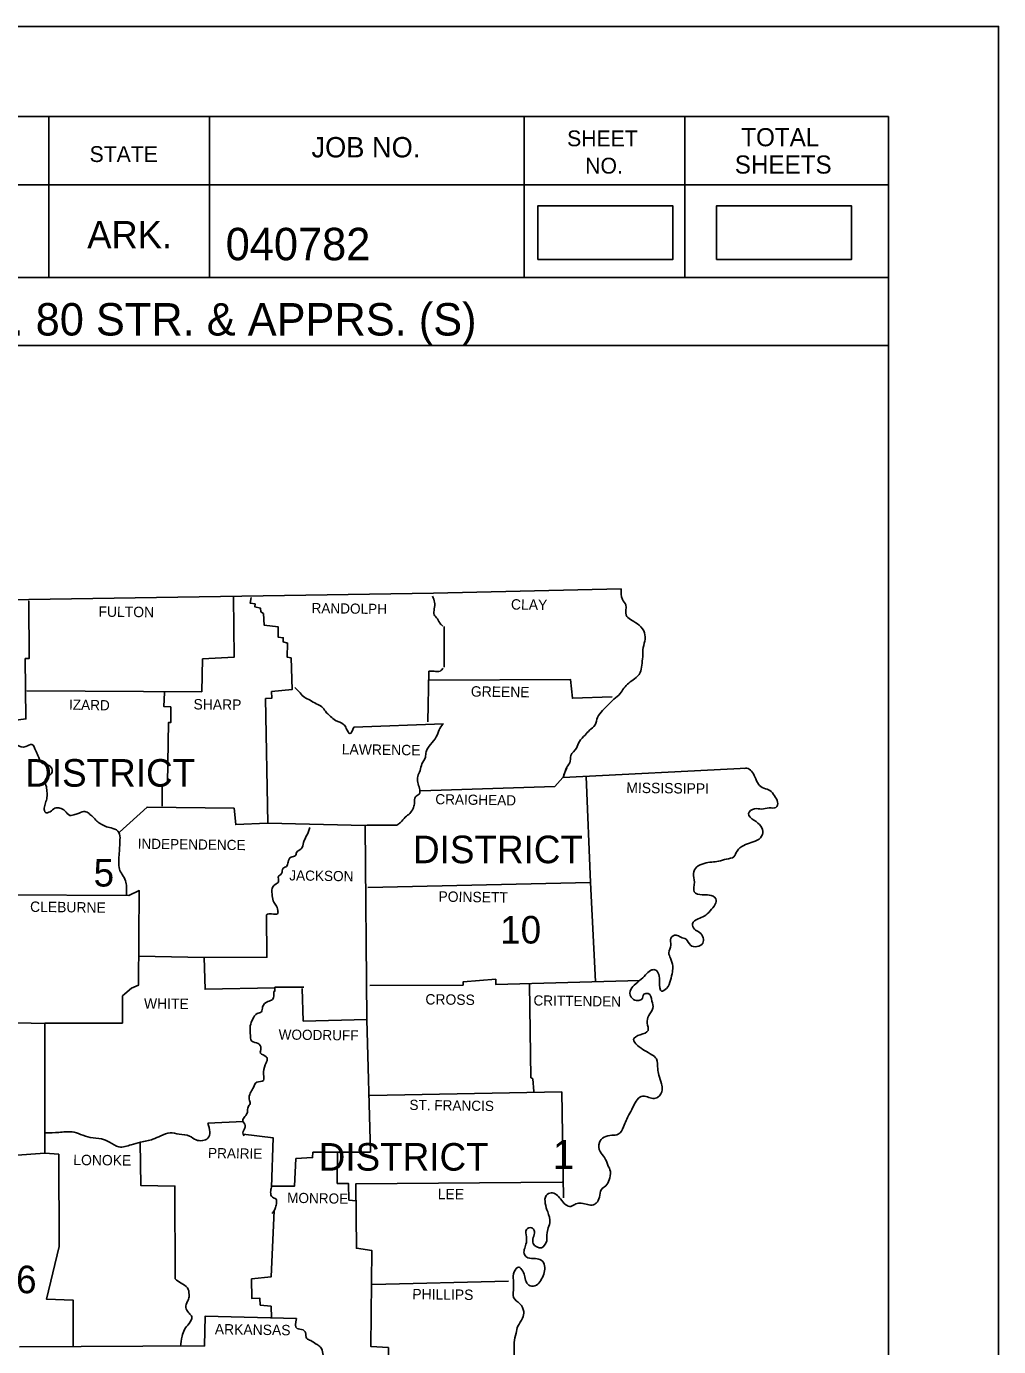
# Model space of a CAD drawing. Extents: x 1382482 to 1385815, y 1168351 to 1170484.
# Drawn here: x 1385395 to 1385815, y 1169914 to 1170484 of the extents above; entities that cross this region are included whole.
import ezdxf

# ---------------------------------------------------------------- set-up
doc = ezdxf.new("R2010")
doc.units = 0
for name, color, linetype in [('Default', 7, 'Continuous'), ('R_Border', 7, 'Continuous'), ('R_Draft', 7, 'Continuous'), ('R_No Plot', 7, 'Continuous')]:
    doc.layers.add(name, color=color, linetype=linetype)

msp = doc.modelspace()

# ---------------------------------------------------------------- linework, layer by layer
at = {"layer": 'Default'}
for p, q in [((1385627.26, 1170159.85), (1385628.51, 1170163.71)), ((1385627.57, 1170161.1), (1385628.82, 1170164.13)), ((1385502.8, 1170069.43), (1385515.22, 1170069.43))]:
    msp.add_line(p, q, dxfattribs=at)
for points in [[(1385079.51, 1170236.59), (1385248.34, 1170236.48), (1385396.51, 1170236.8), (1385571.29, 1170239.51), (1385652.31, 1170241.39)], [(1385484.94, 1170237.74), (1385485.15, 1170211.84), (1385471.58, 1170211.11), (1385471.16, 1170196.91), (1385395.67, 1170197.33)], [(1385492.46, 1170237.63), (1385492.15, 1170235.13), (1385494.23, 1170234.81), (1385494.13, 1170233.56), (1385496.53, 1170233.04), (1385496.74, 1170231.37), (1385497.89, 1170230.64), (1385498.2, 1170225.63), (1385504.15, 1170225), (1385504.15, 1170220.51), (1385506.35, 1170220.2), (1385506.35, 1170218.42), (1385508.23, 1170217.9), (1385508.12, 1170211.84), (1385509.79, 1170211.53), (1385510.21, 1170197.85), (1385501.33, 1170197.02), (1385501.44, 1170194.09), (1385498.72, 1170193.99), (1385499.66, 1170140.12), (1385541.74, 1170139.18), (1385542.47, 1170055.44), (1385515.01, 1170054.71), (1385514.49, 1170068.8)], [(1385396.51, 1170236.17), (1385396.71, 1170211.32), (1385394.94, 1170211.22), (1385395.25, 1170185.22), (1385387.94, 1170184.18), (1385388.57, 1170177.18), (1385391.08, 1170173.94), (1385390.87, 1170165.7), (1385376.67, 1170165.17), (1385376.14, 1170152.44), (1385363.2, 1170152.02), (1385362.57, 1170136.57), (1385363.3, 1170135.31), (1385363.62, 1170110.67), (1385385.96, 1170109.21), (1385385.65, 1170054.19), (1385403.4, 1170053.66), (1385403.4, 1169997.7), (1385389.41, 1169996.66), (1385388.36, 1169984.34), (1385364.87, 1169984.23)], [(1385575.88, 1170225.1), (1385575.88, 1170207.46)], [(1385568.78, 1170183.97), (1385569.31, 1170205.79), (1385569.31, 1170201.93), (1385630.39, 1170202.24), (1385631.22, 1170194.09), (1385648.45, 1170194.72)], [(1385455.08, 1170196.6), (1385454.87, 1170190.54), (1385457.79, 1170190.34), (1385457.9, 1170183.65), (1385456.86, 1170183.65), (1385456.44, 1170157.34), (1385454.04, 1170156.3), (1385454.04, 1170147.53)], [(1385536.83, 1170181.67), (1385575.57, 1170183.03)], [(1385627.26, 1170159.85), (1385706.5, 1170163.92)], [(1385565.65, 1170154.11), (1385623.6, 1170155.99), (1385627.05, 1170159.95)], [(1385637.25, 1170160.36), (1385639.05, 1170114.53), (1385641.18, 1170071.76)], [(1385435.66, 1170136.36), (1385447.56, 1170147.11), (1385485.15, 1170146.59), (1385485.88, 1170139.59), (1385499.56, 1170140.12)], [(1385555.42, 1170139.38), (1385542.68, 1170139.38), (1385541.74, 1170139.18)], [(1385639.05, 1170114.53), (1385542.89, 1170112.34)], [(1385385.96, 1170109.21), (1385439.63, 1170108.9), (1385444.22, 1170111.09), (1385443.91, 1170070.27), (1385440.78, 1170068.91), (1385437.96, 1170066.51), (1385437.02, 1170065.57), (1385436.91, 1170053.87), (1385403.4, 1170053.87)], [(1385499.14, 1170100.65), (1385499.35, 1170082.27), (1385472.2, 1170082.17), (1385444, 1170082.7)], [(1385472.2, 1170082.17), (1385472.62, 1170068.49), (1385502.8, 1170069.03)], [(1385543.73, 1170070.06), (1385584.03, 1170070.27), (1385584.13, 1170071.73), (1385598.12, 1170072.77), (1385598.12, 1170070.58), (1385660.33, 1170072.29)], [(1385502.8, 1170069.43), (1385502.8, 1170067.66), (1385502.27, 1170067.55)], [(1385612.74, 1170070.58), (1385613.26, 1170030.38), (1385614.2, 1170029.75), (1385614.52, 1170024.33)], [(1385612.74, 1170070.58), (1385613.26, 1170030.38), (1385614.2, 1170029.75), (1385614.52, 1170024.33)], [(1385612.74, 1170070.58), (1385613.26, 1170030.38), (1385614.2, 1170029.75), (1385614.52, 1170024.33)], [(1385612.74, 1170070.58), (1385613.26, 1170030.38), (1385614.2, 1170029.75), (1385614.52, 1170024.33)], [(1385612.74, 1170070.58), (1385613.26, 1170030.38), (1385614.2, 1170029.75), (1385614.52, 1170024.33)], [(1385542.47, 1170055.44), (1385544.04, 1169998.22), (1385519.19, 1169998.12), (1385519.08, 1169995.82), (1385511.88, 1169995.4), (1385511.25, 1169983.5), (1385501.35, 1169983.5)], [(1385543.73, 1170022.55), (1385626.63, 1170024.22)], [(1385626.63, 1170024.22), (1385627.46, 1169978.49)], [(1385626.63, 1170024.22), (1385627.46, 1169978.49)], [(1385626.63, 1170024.22), (1385627.46, 1169978.49)], [(1385626.63, 1170024.22), (1385627.46, 1169978.49)], [(1385626.63, 1170024.22), (1385627.46, 1169978.49)], [(1385626.63, 1170024.22), (1385627.46, 1169978.49)], [(1385626.63, 1170024.22), (1385627.46, 1169978.49)], [(1385626.63, 1170024.22), (1385627.46, 1169978.49)], [(1385473.87, 1170010.65), (1385489.12, 1170011.38)], [(1385489.01, 1170005.95), (1385502.07, 1170004.28), (1385501.33, 1169982.98)], [(1385403.4, 1169997.7), (1385409.45, 1169997.28), (1385409.56, 1169957.4), (1385404.13, 1169934.74), (1385415.72, 1169934.22), (1385415.61, 1169914.26)], [(1385444.64, 1170002.5), (1385444.85, 1169983.81), (1385459.57, 1169983.5), (1385459.67, 1169943.41)], [(1385529.84, 1169998.16), (1385529.73, 1169984.65), (1385534.54, 1169984.65), (1385534.75, 1169977.45), (1385537.83, 1169977.13)], [(1385542.13, 1169891.94), (1385551.87, 1169892.56), (1385551.77, 1169913.76), (1385544.14, 1169914.28), (1385544.56, 1169955.73), (1385537.98, 1169956.67), (1385537.77, 1169984.55), (1385626.84, 1169985.17)], [(1385502.48, 1169972.96), (1385501.23, 1169944.35), (1385492.67, 1169943.41), (1385492.88, 1169934.95), (1385496.32, 1169935.06), (1385496.43, 1169932.13), (1385501.13, 1169931.61), (1385501.28, 1169926.57)], [(1385544.77, 1169941.01), (1385603.66, 1169942.47)], [(1385512.09, 1169926.28), (1385472.62, 1169927.33), (1385472.41, 1169914.49), (1385392.54, 1169914.17)]]:
    msp.add_lwpolyline(points, dxfattribs=at)
for points in [[(1385570.77, 1170238.16), (1385571.71, 1170235.55), (1385571.6, 1170232.73), (1385571.6, 1170230.12), (1385572.96, 1170228.34), (1385574.32, 1170226.15), (1385575.36, 1170225.21)], [(1385652.31, 1170241.39), (1385652.84, 1170236.8), (1385654.3, 1170234.4), (1385654.51, 1170230.01), (1385656.28, 1170228.13), (1385659.31, 1170226.25), (1385662.02, 1170223.22), (1385662.65, 1170219.68), (1385661.82, 1170216.02), (1385661.61, 1170211.95), (1385661.19, 1170208.4), (1385660.56, 1170205.16), (1385658.06, 1170202.55), (1385655.66, 1170200.67), (1385653.46, 1170198.48), (1385651.9, 1170196.18), (1385649.18, 1170193.68), (1385646.47, 1170191.07), (1385644.27, 1170188.77), (1385642.08, 1170185.85), (1385641.04, 1170182.61), (1385638.64, 1170180.31), (1385636.76, 1170178.22), (1385634.25, 1170175.41), (1385633, 1170172.59), (1385630.6, 1170169.35), (1385630.07, 1170166.22), (1385628.51, 1170163.71), (1385628.4, 1170163.29)], [(1385575.47, 1170207.15), (1385574.11, 1170205.79), (1385571.5, 1170205.79), (1385569.31, 1170205.79)], [(1385511.36, 1170198.79), (1385513.66, 1170196.39), (1385515.64, 1170194.41), (1385517.94, 1170193.26), (1385520.65, 1170191.69), (1385523.05, 1170190.44), (1385524.62, 1170188.46), (1385526.81, 1170186.26), (1385529, 1170184.49), (1385532.45, 1170182.82), (1385533.6, 1170181.04), (1385535.16, 1170178.85), (1385536.83, 1170181.67)], [(1385575.26, 1170182.92), (1385573.69, 1170180.42), (1385572.44, 1170177.49), (1385569.93, 1170174.15), (1385568.05, 1170170.92), (1385567.74, 1170168.72), (1385566.28, 1170165.8), (1385565.44, 1170162.88), (1385564.5, 1170160.37), (1385564.5, 1170157.76), (1385565.23, 1170155.15), (1385565.03, 1170152.75), (1385563.46, 1170151.6), (1385563.04, 1170148.57), (1385562.42, 1170146.48), (1385561.06, 1170144.4), (1385559.07, 1170142.83), (1385556.99, 1170140.43), (1385555.42, 1170139.38)], [(1385391.08, 1170173.94), (1385395.25, 1170173.21), (1385397.76, 1170174.15), (1385399.53, 1170171.44), (1385400.47, 1170169.35), (1385402.04, 1170166.32), (1385404.54, 1170165.38), (1385406.42, 1170163.71), (1385406.42, 1170161.94), (1385404.75, 1170160.27), (1385403.5, 1170158.6), (1385403.92, 1170156.61), (1385404.34, 1170153.9), (1385404.34, 1170151.29), (1385403.71, 1170148.89), (1385403.19, 1170146.69), (1385403.71, 1170144.81), (1385405.69, 1170145.13), (1385407.78, 1170146.69), (1385409.97, 1170146.69), (1385412.06, 1170145.54), (1385414.26, 1170143.56), (1385416.45, 1170143.98), (1385418.22, 1170144.5), (1385420.73, 1170145.23), (1385422.5, 1170144.29), (1385424.07, 1170143.04), (1385425.95, 1170141.05), (1385427.72, 1170139.8), (1385430.02, 1170138.65), (1385432.84, 1170137.92), (1385435.45, 1170136.15), (1385435.87, 1170133.12), (1385435.76, 1170130.51), (1385435.56, 1170127.27), (1385435.35, 1170123.72), (1385435.66, 1170120.28), (1385436.81, 1170117.98), (1385438.27, 1170115.27), (1385438.69, 1170112.76), (1385438.58, 1170108.79)], [(1385705.36, 1170163.82), (1385706.5, 1170163.92), (1385710.05, 1170160.16), (1385711.62, 1170157.03), (1385713.92, 1170155.25), (1385716.53, 1170154.31), (1385718.51, 1170151.91), (1385719.87, 1170149.3), (1385719.14, 1170147.01), (1385716.21, 1170146.8), (1385712.98, 1170146.28), (1385709.85, 1170146.38), (1385707.34, 1170144.29), (1385709.64, 1170141.47), (1385712.66, 1170138.86), (1385713.5, 1170136.04), (1385711.83, 1170133.33), (1385708.49, 1170131.87), (1385705.25, 1170130.61), (1385702.33, 1170128.11), (1385700.97, 1170125.71), (1385697.73, 1170124.66), (1385694.39, 1170123.72), (1385691.47, 1170123.41), (1385688.13, 1170122.78), (1385684.89, 1170121.22), (1385683.53, 1170118.5), (1385683.95, 1170114.64), (1385683.85, 1170110.57), (1385687.29, 1170109.21), (1385690.32, 1170109.11), (1385693.24, 1170107.54), (1385692.93, 1170105.24), (1385690.74, 1170102.32), (1385688.13, 1170100.02), (1385685.52, 1170098.87), (1385683.12, 1170096.68), (1385683.95, 1170094.49), (1385686.14, 1170093.03), (1385687.71, 1170090.63), (1385687.5, 1170088.43), (1385685, 1170086.87), (1385682.28, 1170087.49), (1385680.3, 1170090.1), (1385678, 1170090.94), (1385676.02, 1170091.88), (1385673.72, 1170090.52), (1385673.72, 1170087.49), (1385672.88, 1170084.26), (1385673.61, 1170081.85), (1385674.55, 1170078.51), (1385674.45, 1170076.01), (1385673.61, 1170072.46), (1385671.84, 1170068.8), (1385669.75, 1170067.66), (1385668.92, 1170071.62), (1385668.5, 1170074.86), (1385667.25, 1170076.74), (1385665.57, 1170076.84), (1385663.38, 1170075.28), (1385660.98, 1170072.88), (1385657.95, 1170070.27), (1385656.18, 1170067.66), (1385657.12, 1170064.42), (1385659.41, 1170063.58), (1385661.19, 1170064.21), (1385662.13, 1170066.3), (1385663.9, 1170066.61), (1385665.57, 1170063.37)], [(1385517.83, 1170138.24), (1385516.58, 1170135), (1385515.12, 1170131.87), (1385514.18, 1170129.15), (1385512.19, 1170127.59), (1385511.57, 1170126.12), (1385509.79, 1170125.5), (1385508.43, 1170123.41), (1385507.81, 1170121.53), (1385506.35, 1170120.69), (1385505.62, 1170118.4), (1385504.26, 1170117.15), (1385504.36, 1170115.06), (1385502.8, 1170113.6), (1385501.54, 1170111.92), (1385501.54, 1170109.63), (1385502.07, 1170106.6), (1385503.11, 1170104.82), (1385504.05, 1170102.53), (1385503.94, 1170101.07), (1385501.33, 1170101.07), (1385499.14, 1170100.65)], [(1385502.27, 1170067.55), (1385501.75, 1170064.11), (1385499.77, 1170063.17), (1385497.47, 1170060.87), (1385496.95, 1170058.78), (1385495.07, 1170057.95), (1385493.29, 1170055.75), (1385492.15, 1170052.72), (1385492.15, 1170049.59), (1385492.88, 1170046.04), (1385495.49, 1170045.1), (1385496.74, 1170043.01), (1385496.53, 1170040.82), (1385499.04, 1170039.36), (1385499.46, 1170038.11), (1385499.04, 1170036.75), (1385497.89, 1170032.89), (1385497.99, 1170030.28), (1385497.78, 1170029.13), (1385494.97, 1170028.4), (1385493.29, 1170025.58), (1385492.15, 1170023.59), (1385491.73, 1170020.98), (1385492.04, 1170019.1), (1385491.21, 1170017.64), (1385490.89, 1170015.45), (1385489.85, 1170013.57), (1385488.91, 1170011.8), (1385489.95, 1170009.71), (1385489.64, 1170008.25), (1385489.01, 1170005.95), (1385489.54, 1170005.22)], [(1385665.57, 1170063.37), (1385665.99, 1170060.35), (1385664.22, 1170057.11), (1385663.59, 1170053.87), (1385663.9, 1170050.64), (1385660.56, 1170048.86), (1385657.64, 1170046.77), (1385659.31, 1170044.27), (1385662.44, 1170041.97), (1385665.57, 1170040.2), (1385667.56, 1170038.42), (1385668.08, 1170034.14), (1385668.6, 1170031.43), (1385669.65, 1170027.67), (1385670.06, 1170025.06), (1385668.18, 1170021.92), (1385665.99, 1170021.3), (1385663.7, 1170022.03), (1385660.98, 1170022.24), (1385658.79, 1170020.15), (1385657.22, 1170017.23), (1385655.66, 1170014.3), (1385654.51, 1170011.8), (1385653.36, 1170009.08), (1385651.06, 1170005.95), (1385648.24, 1170005.43), (1385644.9, 1170004.59), (1385642.92, 1170002.29), (1385643.23, 1169998.43), (1385645.11, 1169995.82), (1385646.57, 1169992.58), (1385647.62, 1169989.77), (1385647.09, 1169986.22), (1385645.63, 1169983.61), (1385643.75, 1169982.04), (1385642.92, 1169978.7), (1385641.56, 1169976.19), (1385640.31, 1169975.36), (1385637.8, 1169975.57), (1385635.09, 1169976.09), (1385632.79, 1169975.88), (1385630.6, 1169974.73), (1385628.4, 1169975.46), (1385626.11, 1169977.97), (1385624.23, 1169979.85), (1385622.14, 1169980.58), (1385619.95, 1169979.43), (1385619.53, 1169975.98), (1385620.57, 1169972.43), (1385621.51, 1169967.63), (1385620.57, 1169964.71), (1385620.26, 1169959.9)], [(1385403.61, 1170006.47), (1385409.45, 1170006.68), (1385415.19, 1170006.89), (1385418.85, 1170005.84), (1385423.03, 1170004.49), (1385427.93, 1170003.86), (1385431.38, 1170002.5), (1385435.45, 1170000.42), (1385440.67, 1170001.36), (1385444.74, 1170002.4), (1385450.07, 1170003.76), (1385453.51, 1170005.22), (1385457.48, 1170006.47), (1385461.45, 1170005.95), (1385465.94, 1170005.11), (1385468.76, 1170003.44), (1385473.87, 1170004.17), (1385473.87, 1170010.65)], [(1385501.33, 1169982.98), (1385500.92, 1169980.89), (1385501.75, 1169978.7), (1385503.21, 1169977.97), (1385503.42, 1169975.88), (1385502.9, 1169973.79), (1385502.48, 1169972.96), (1385501.54, 1169971.7)], [(1385620.26, 1169959.9), (1385617.86, 1169956.88), (1385614.31, 1169958.76), (1385614.31, 1169961.26), (1385614.83, 1169963.87), (1385613.58, 1169965.54), (1385611.38, 1169964.81), (1385611.38, 1169961.58), (1385611.18, 1169958.44), (1385610.55, 1169953.95), (1385612.01, 1169952.6), (1385615.35, 1169952.18), (1385617.75, 1169951.55), (1385619.22, 1169949.15), (1385619.11, 1169946.23), (1385617.96, 1169943.41), (1385616.29, 1169941.11), (1385613.68, 1169940.28), (1385611.59, 1169941.63), (1385610.76, 1169944.35), (1385609.82, 1169946.75), (1385608.04, 1169948.52), (1385606.16, 1169946.54), (1385605.75, 1169942.89), (1385605.85, 1169939.75), (1385605.85, 1169935.47), (1385608.57, 1169932.65), (1385610.24, 1169929.42), (1385609.71, 1169926.49), (1385607.73, 1169923.05), (1385606.89, 1169920.02), (1385606.06, 1169915.95), (1385606.16, 1169911.46), (1385605.43, 1169907.07), (1385603.97, 1169904.15), (1385601.26, 1169901.75), (1385599.48, 1169900.18), (1385598.02, 1169898.62), (1385597.29, 1169895.48), (1385596.77, 1169893.29), (1385594.78, 1169890.68), (1385593.22, 1169890.47), (1385591.96, 1169891.52), (1385591.55, 1169893.29), (1385591.55, 1169895.07), (1385590.71, 1169896.84), (1385588.1, 1169897.57), (1385586.01, 1169897.47), (1385585.07, 1169896.01), (1385586.43, 1169891.93), (1385586.95, 1169889.32), (1385586.22, 1169885.77), (1385586.64, 1169885.36), (1385582.88, 1169883.37), (1385579.85, 1169883.06), (1385577.35, 1169882.33), (1385574.94, 1169880.76), (1385573.8, 1169878.47), (1385572.13, 1169876.59), (1385570.66, 1169874.81), (1385568.68, 1169873.98), (1385566.49, 1169874.39), (1385563.56, 1169874.71), (1385561.89, 1169872.62), (1385562.42, 1169869.59), (1385564.4, 1169867.82), (1385567.32, 1169866.98), (1385570.35, 1169867.19), (1385573.27, 1169867.5), (1385575.99, 1169866.04), (1385575.47, 1169863.22), (1385572.86, 1169861.86), (1385568.99, 1169861.45), (1385565.86, 1169861.76), (1385562.1, 1169860.92), (1385560.22, 1169858.52), (1385561.27, 1169854.87), (1385565.34, 1169853.41), (1385567.22, 1169849.96), (1385567.32, 1169846.73), (1385565.97, 1169842.44), (1385564.09, 1169840.46), (1385560.43, 1169839.63), (1385557.61, 1169839.1), (1385557.19, 1169834.3), (1385555.94, 1169831.9), (1385553.75, 1169831.17), (1385550.62, 1169832.73), (1385548.74, 1169833.47), (1385546.44, 1169834.51), (1385543.52, 1169836.28), (1385541.32, 1169835.97), (1385541.95, 1169831.38), (1385542.16, 1169831.17), (1385544.67, 1169827.72), (1385547.17, 1169825.01), (1385548.32, 1169821.77)], [(1385459.67, 1169943.41), (1385462.28, 1169941.63), (1385465, 1169939.54), (1385465.73, 1169936.73), (1385465.52, 1169934.74), (1385464.69, 1169933.07), (1385464.48, 1169930.46), (1385465.73, 1169928.58), (1385466.88, 1169927.02), (1385465.73, 1169924.2), (1385463.75, 1169921.59), (1385462.7, 1169918.66), (1385461.97, 1169914.28)], [(1385512.09, 1169926.28), (1385512.4, 1169922), (1385514.91, 1169921.38), (1385515.95, 1169920.23), (1385516.47, 1169917.83), (1385518.25, 1169916.78), (1385520.65, 1169915.32), (1385522.11, 1169914.28), (1385523.16, 1169912.61), (1385523.78, 1169909.89), (1385525.45, 1169908.12), (1385527.75, 1169907.28), (1385529.42, 1169905.3), (1385530.47, 1169902.48), (1385532.14, 1169901.23), (1385533.81, 1169899.03), (1385534.64, 1169898.09), (1385536.1, 1169895.59), (1385537.57, 1169894.34), (1385538.61, 1169893.6), (1385540.28, 1169893.08), (1385542.37, 1169891.73), (1385543.73, 1169889.64), (1385543.73, 1169888.07), (1385543.2, 1169885.67), (1385542.79, 1169883.16), (1385542.58, 1169880.34), (1385542.37, 1169877.84), (1385543.31, 1169875.75), (1385542.79, 1169872.62), (1385541.74, 1169870.95), (1385541.64, 1169868.65), (1385541.32, 1169865.21), (1385540.91, 1169863.22), (1385539.97, 1169859.99), (1385538.61, 1169858.31)]]:
    msp.add_spline(points, degree=3, dxfattribs=at)
at = {"layer": 'R_Border'}
for p, q in [((1382605.96, 1170445.2), (1385767.76, 1170445.2)), ((1385405.16, 1170445.2), (1385405.16, 1170375.8)), ((1385474.56, 1170445.2), (1385474.56, 1170375.8)), ((1385610.36, 1170445.2), (1385610.36, 1170375.8)), ((1385679.76, 1170445.2), (1385679.76, 1170375.8)), ((1385767.76, 1168390.6), (1385767.76, 1170445.2)), ((1385767.76, 1170415.8), (1385336.76, 1170415.8)), ((1385767.76, 1170416), (1385767.76, 1170416)), ((1385767.76, 1170375.8), (1385336.76, 1170375.8)), ((1385366.36, 1170375.8), (1385767.76, 1170375.8)), ((1385767.76, 1170346.4), (1385141.36, 1170346.4))]:
    msp.add_line(p, q, dxfattribs=at)
at = {"layer": 'R_Draft'}
for points in [[(1385616.29, 1170383.57), (1385674.63, 1170383.57), (1385674.63, 1170406.67), (1385616.29, 1170406.67)], [(1385693.43, 1170383.57), (1385751.76, 1170383.57), (1385751.76, 1170406.67), (1385693.43, 1170406.67)]]:
    msp.add_lwpolyline(points, close=True, dxfattribs=at)
at = {"layer": 'R_No Plot'}
msp.add_line((1382481.95, 1170484.15), (1385815.28, 1170484.15), dxfattribs=at)
msp.add_lwpolyline([(1382481.88, 1170484.15), (1385815.28, 1170484.15), (1385815.28, 1168350.77), (1382481.88, 1168350.77)], close=True, dxfattribs=at)

# ---------------------------------------------------------------- texts
at = {"layer": 'Default'}
for s, height, rotation, p in [('FULTON', 4.489, 359.4996, (1385426.58, 1170229.28)), ('RANDOLPH', 4.386, 359.2584, (1385518.56, 1170230.85)), ('CLAY', 4.489, 359.2258, (1385604.7, 1170232.41)), ('GREENE', 4.49, 359.2361, (1385587.37, 1170194.83)), ('IZARD', 4.385, 358.9259, (1385413.84, 1170189.19)), ('SHARP', 4.489, 359.3905, (1385467.61, 1170189.29)), ('LAWRENCE', 4.49, 359.2678, (1385531.61, 1170169.87)), ('MISSISSIPPI', 4.4891, 359.3097, (1385654.51, 1170153.27)), ('CRAIGHEAD', 4.386, 359.1159, (1385572.02, 1170148.36)), ('INDEPENDENCE', 4.3845, 359.2188, (1385443.49, 1170129.15)), ('JACKSON', 4.384, 359.1352, (1385508.96, 1170115.47)), ('CLEBURNE', 4.489, 359.2535, (1385397.03, 1170101.9)), ('POINSETT', 4.489, 359.1987, (1385573.38, 1170106.29)), ('CROSS', 4.489, 359.384, (1385567.74, 1170061.91)), ('WHITE', 4.49, 359.3139, (1385446.21, 1170060.14)), ('CRITTENDEN', 4.386, 359.213, (1385614.41, 1170061.49)), ('WOODRUFF', 4.384, 359.2748, (1385504.36, 1170046.77)), ('ST. FRANCIS', 4.3845, 359.2216, (1385560.85, 1170016.39)), ('PRAIRIE', 4.386, 359.2116, (1385473.87, 1169995.61)), ('LONOKE', 4.49, 359.4974, (1385415.72, 1169992.58)), ('MONROE', 4.384, 359.0331, (1385508.02, 1169976.3)), ('LEE', 4.49, 359.4327, (1385573.07, 1169977.86)), ('PHILLIPS', 4.489, 359.318, (1385562.1, 1169934.64)), ('ARKANSAS', 4.489, 359.2678, (1385476.8, 1169919.5))]:
    msp.add_text(s, height=height, rotation=rotation, dxfattribs=at).set_placement(p)
for s, height, p in [('DISTRICT', 11.903, (1385394.95, 1170155.93)), ('DISTRICT', 11.903, (1385562.42, 1170122.89)), ('5', 11.9, (1385424.48, 1170112.83)), ('10', 11.903, (1385600.03, 1170088.22)), ('1', 12.53, (1385622.77, 1169990.91)), ('DISTRICT', 11.903, (1385521.69, 1169990.18)), ('DISTRICT 6', 11.903, (1385313.18, 1169937.25))]:
    msp.add_text(s, height=height, dxfattribs=at).set_placement(p)
at = {"layer": 'R_Border'}
for s, height, p in [('JOB NO.', 8.792, (1385518.56, 1170427.6)), ('SHEET', 6.84, (1385628.96, 1170432.4)), ('TOTAL', 7.819, (1385704.16, 1170432.4)), ('STATE', 6.84, (1385422.76, 1170425.6)), ('NO.', 6.84, (1385636.76, 1170420.6)), ('SHEETS', 7.819, (1385701.36, 1170420.6)), ('ARK.', 11.723, (1385421.76, 1170388.4)), ('040782', 14, (1385481.52, 1170383.19)), ('HWY. 80 STR. & APPRS. (S)', 14, (1385345.39, 1170350.7))]:
    msp.add_text(s, height=height, dxfattribs=at).set_placement(p)

doc.saveas('drawing.dxf')
